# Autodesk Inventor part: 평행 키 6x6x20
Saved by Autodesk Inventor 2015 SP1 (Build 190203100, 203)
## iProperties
Created: 2026-07
Part Number: 평행 키 6x6x20
Material: 일반
Document SubType Name: Modeling
Designer: user
Density: 1 g/cm^3
Appearance: 기본값
Author: user
Author: jhkim
Creation Date: 2026-07-01
Sending System: Autodesk Inventor 2027
Preprocessor: ST-DEVELOPER v20.1
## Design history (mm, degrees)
node "평행 키 6x6x201"
body "Solid1"
node "기준1"
